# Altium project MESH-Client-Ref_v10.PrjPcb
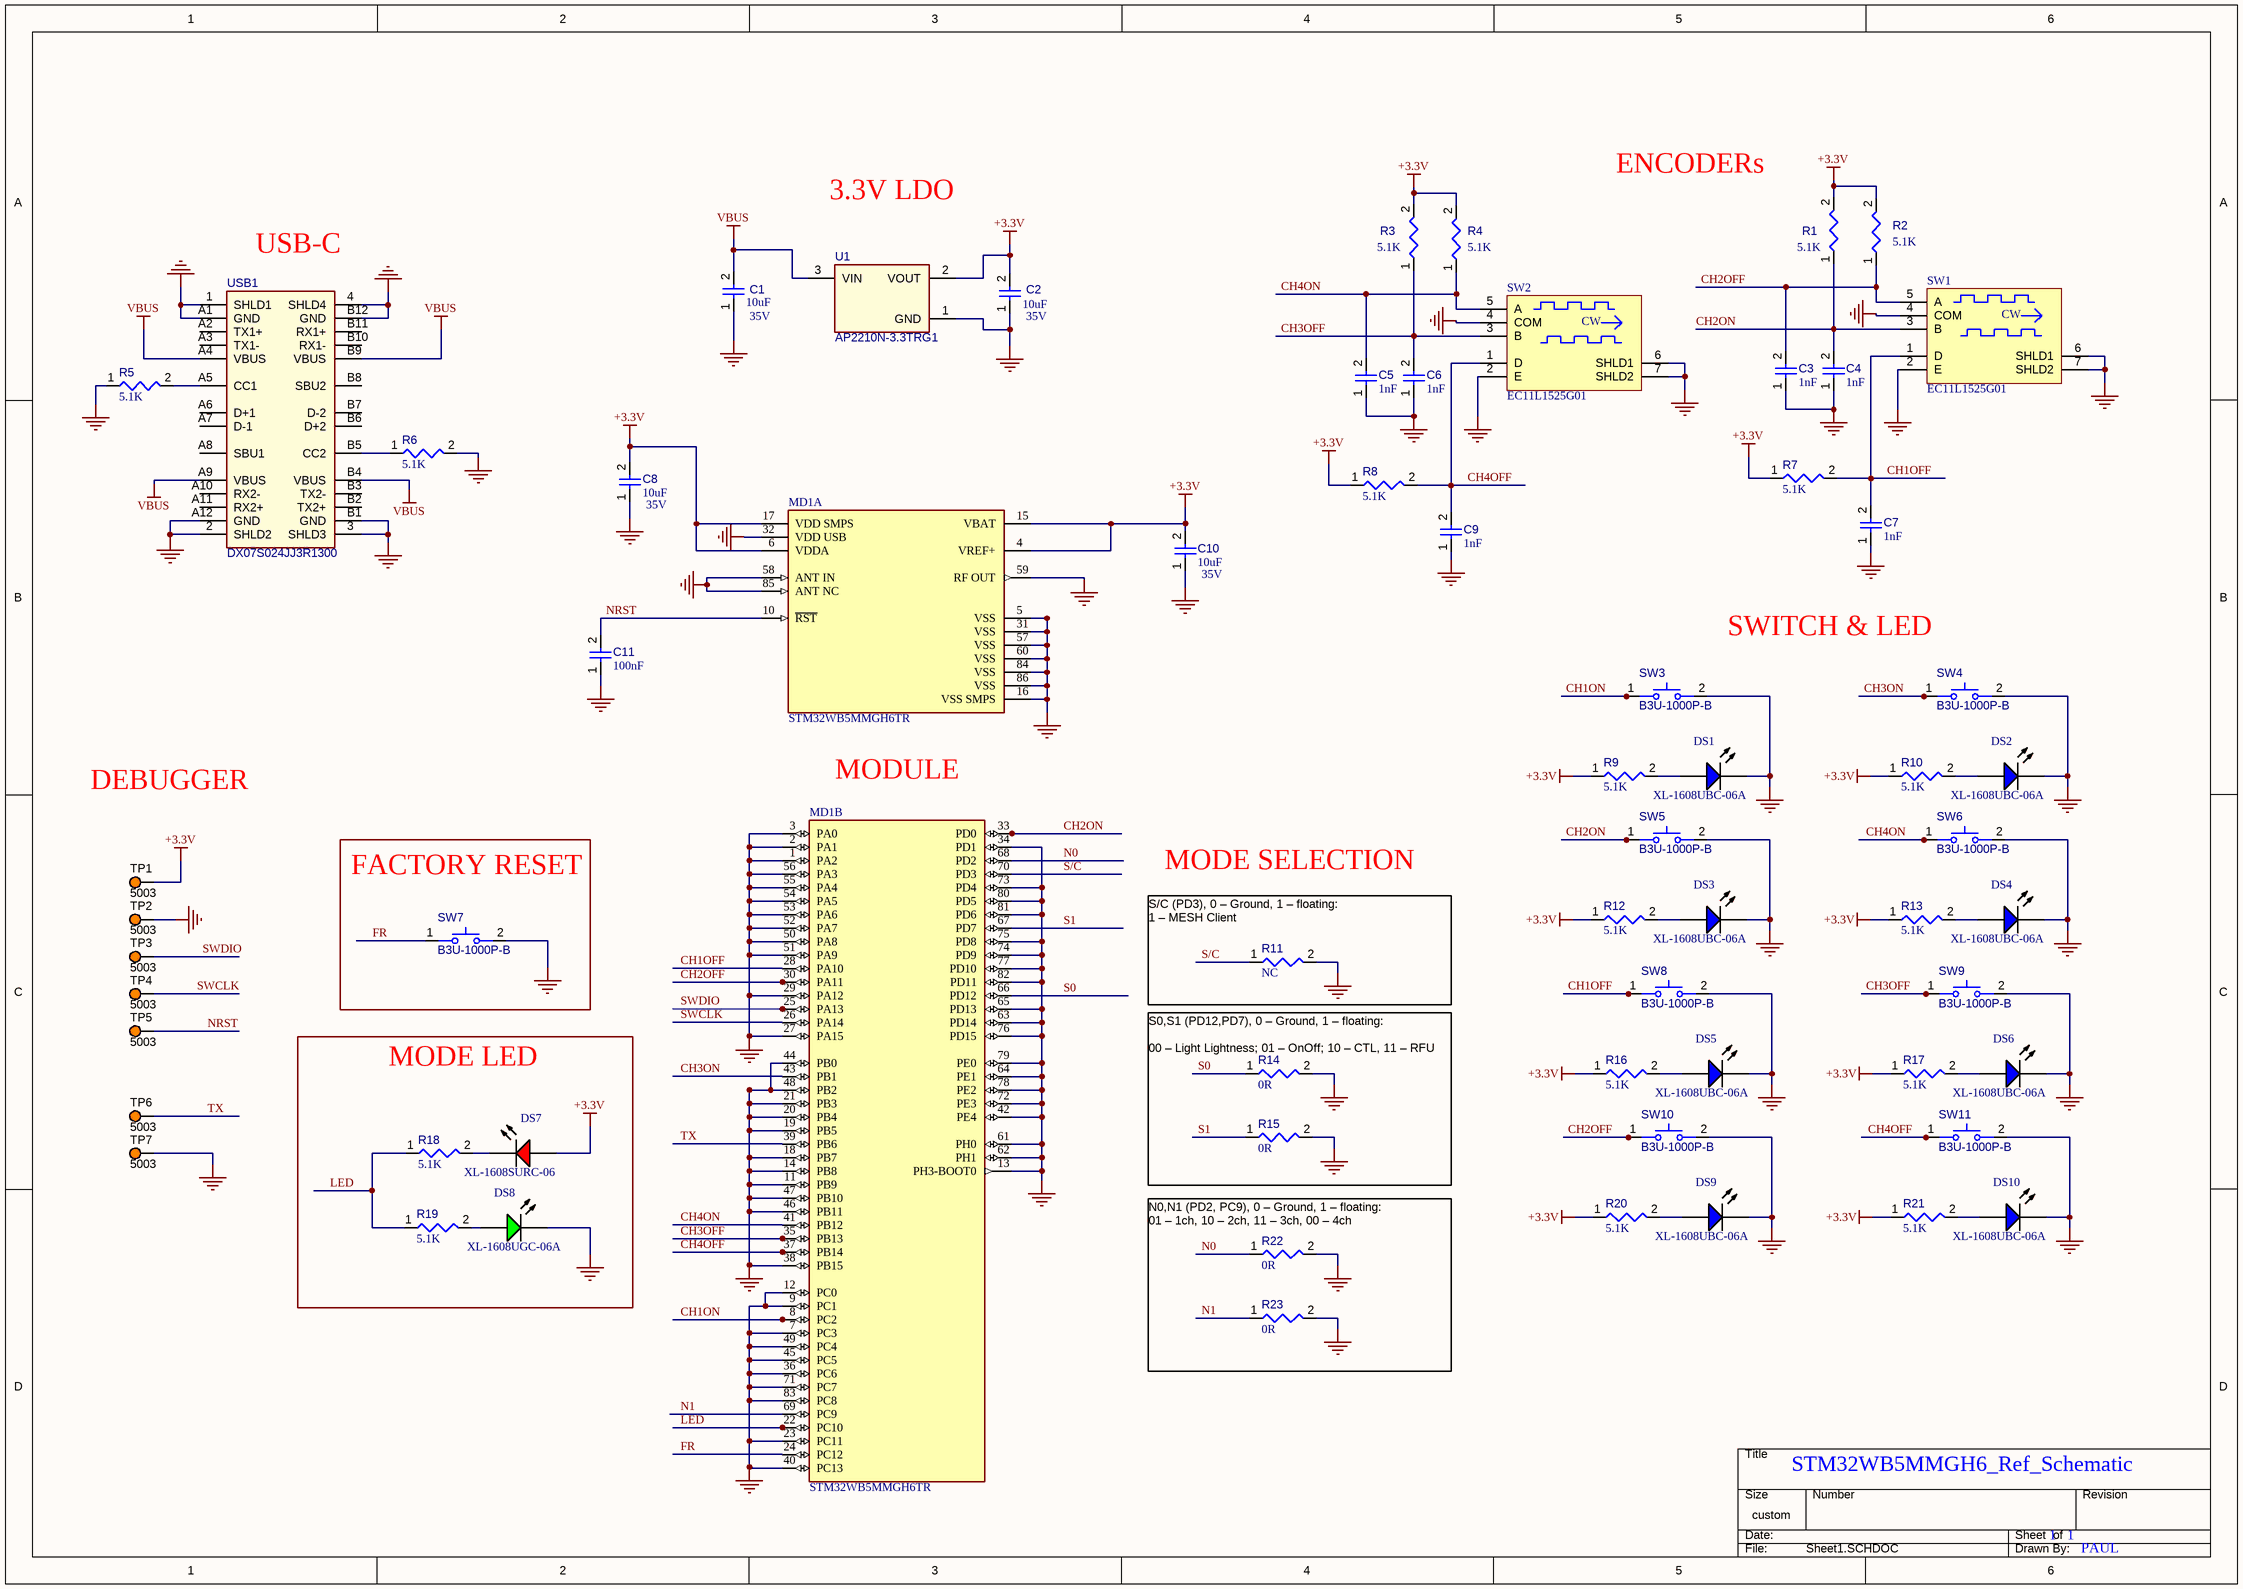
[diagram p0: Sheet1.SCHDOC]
1 sheet, 65 parts. Net scope: global (net labels, ports and power ports of the same name join across sheets).
Board file: PCB1.PcbDoc

## Sheet Sheet1.SCHDOC
size 420 x 297 mm; SheetNumber: 1; SheetTotal: 1

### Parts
C1  Voltage Rating: 35V  [C0603]  (hidden comment: 10uF)
C2  Voltage Rating: 35V  [C0603]  (hidden comment: 10uF)
C3  1nF  [C0603]
C4  1nF  [C0603]
C5  1nF  [C0603]
C6  1nF  [C0603]
C7  1nF  [C0603]
C8  Voltage Rating: 35V  [C0603]  (hidden comment: 10uF)
C9  1nF  [C0603]
C10  Voltage Rating: 35V  [C0603]  (hidden comment: 10uF)
C11  value 100nF  [C0603]  (hidden comment: 0.1uF)
DS1  XL-1608UBC-06A  [LED0603]
DS2  XL-1608UBC-06A  [LED0603]
DS3  XL-1608UBC-06A  [LED0603]
DS4  XL-1608UBC-06A  [LED0603]
DS5  XL-1608UBC-06A  [LED0603]
DS6  XL-1608UBC-06A  [LED0603]
DS7  XL-1608SURC-06  [LED0603]
DS8  XL-1608UGC-06A  [LED0603]
DS9  XL-1608UBC-06A  [LED0603]
DS10  XL-1608UBC-06A  [LED0603]
MD1  STM32WB5MMGH6TR  [FP-STM32WB5MMGH6TR-MFG]  (parts A,B of 2)
R1  5.1K  [R0603]
R2  5.1K  [R0603]
R3  5.1K  [R0603]
R4  5.1K  [R0603]
R5  5.1K  [R0603]
R6  5.1K  [R0603]
R7  5.1K  [R0603]
R8  5.1K  [R0603]
R9  5.1K  [R0603]
R10  5.1K  [R0603]
R11  NC  [R0402]  (no BOM)
R12  5.1K  [R0603]
R13  5.1K  [R0603]
R14  0R  [R0402]
R15  0R  [R0402]
R16  5.1K  [R0603]
R17  5.1K  [R0603]
R18  5.1K  [R0603]
R19  5.1K  [R0603]
R20  5.1K  [R0603]
R21  5.1K  [R0603]
R22  0R  [R0402]
R23  0R  [R0402]
SW1  EC11L1525G01  [EC11L1525G01]
SW2  EC11L1525G01  [EC11L1525G01]
SW3  B3U-1000P-B  [OMRON-B3U-1000P-2-B_V]
SW4  B3U-1000P-B  [OMRON-B3U-1000P-2-B_V]
SW5  B3U-1000P-B  [OMRON-B3U-1000P-2-B_V]
SW6  B3U-1000P-B  [OMRON-B3U-1000P-2-B_V]
SW7  B3U-1000P-B  [OMRON-B3U-1000P-2-B_V]
SW8  B3U-1000P-B  [OMRON-B3U-1000P-2-B_V]
SW9  B3U-1000P-B  [OMRON-B3U-1000P-2-B_V]
SW10  B3U-1000P-B  [OMRON-B3U-1000P-2-B_V]
SW11  B3U-1000P-B  [OMRON-B3U-1000P-2-B_V]
TP1  5003  [KSTN-5003]  (no BOM)
TP2  5003  [KSTN-5003]  (no BOM)
TP3  5003  [KSTN-5003]  (no BOM)
TP4  5003  [KSTN-5003]  (no BOM)
TP5  5003  [KSTN-5003]  (no BOM)
TP6  5003  [KSTN-5003]  (no BOM)
TP7  5003  [KSTN-5003]  (no BOM)
U1  AP2210N-3.3TRG1  [SOT23-3]
USB1  DX07S024JJ3R1300  [JAE-DX07S024JJ3_V]

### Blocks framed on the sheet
FACTORY RESET: SW7
MODE LED: DS7 DS8 R18 R19

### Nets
+3.3V: C2.2 C8.2 C10.2 DS7.1(A) MD1.4(VREF+) MD1.6(VDDA) MD1.15(VBAT) MD1.17(VDD_SMPS) R1.2 R2.2 R3.2 R4.2 R7.1 R8.1 R9.1 R10.1 R12.1 R13.1 R16.1 R17.1 R20.1 R21.1 TP1.1 U1.2(VOUT)
GND: C1.1 C2.1 C3.1 C4.1 C5.1 C6.1 C7.1 C8.1 C9.1 C10.1 C11.1 DS1.2(K) DS2.2(K) DS3.2(K) DS4.2(K) DS5.2(K) DS6.2(K) DS8.2(K) DS9.2(K) DS10.2(K) MD1.1(PA2) MD1.2(PA1) MD1.3(PA0) MD1.5(VSS) MD1.7(PC3) MD1.9(PC1) MD1.11(PB9) MD1.12(PC0) MD1.13(PH3-BOOT0) MD1.14(PB8) MD1.16(VSS_SMPS) MD1.18(PB7) MD1.19(PB5) MD1.20(PB4) MD1.21(PB3) MD1.23(PC11) MD1.27(PA15) MD1.29(PA12) MD1.31(VSS) MD1.32(VDD_USB) MD1.34(PD1) MD1.36(PC6) MD1.38(PB15) MD1.40(PC13) MD1.42(PE4) MD1.44(PB0) MD1.45(PC5) MD1.46(PB11) MD1.47(PB10) MD1.48(PB2) MD1.49(PC4) MD1.50(PA8) MD1.51(PA9) MD1.52(PA7) MD1.53(PA6) MD1.54(PA5) MD1.55(PA4) MD1.56(PA3) MD1.57(VSS) MD1.58(ANT_IN) MD1.59(RF_OUT) MD1.60(VSS) MD1.61(PH0) MD1.62(PH1) MD1.63(PD14) MD1.64(PE1) MD1.65(PD13) MD1.71(PC7) MD1.72(PE3) MD1.73(PD4) MD1.74(PD9) MD1.75(PD8) MD1.76(PD15) MD1.77(PD10) MD1.78(PE2) MD1.79(PE0) MD1.80(PD5) MD1.81(PD6) MD1.82(PD11) MD1.83(PC8) MD1.84(VSS) MD1.85(ANT_NC) MD1.86(VSS) R5.1 R6.2 R11.2 R14.2 R15.2 R22.2 R23.2 SW1.2(E) SW1.4(COM) SW1.6(SHLD1) SW1.7(SHLD2) SW2.2(E) SW2.4(COM) SW2.6(SHLD1) SW2.7(SHLD2) SW3.2 SW4.2 SW5.2 SW6.2 SW7.2 SW8.2 SW9.2 SW10.2 SW11.2 TP2.1 TP7.1 U1.1(GND) USB1.1(SHLD1) USB1.2(SHLD2) USB1.3(SHLD3) USB1.4(SHLD4) USB1.A1(GND) USB1.A12(GND) USB1.B1(GND) USB1.B12(GND)
VBUS: C1.2 U1.3(VIN) USB1.A4(VBUS) USB1.A9(VBUS) USB1.B4(VBUS) USB1.B9(VBUS)
CH1OFF: C7.2 MD1.28(PA10) R7.2 SW1.1(D) SW8.1
CH1ON: MD1.8(PC2) SW3.1
CH2OFF: C3.2 MD1.30(PA11) R2.1 SW1.5(A) SW10.1
CH2ON: C4.2 MD1.33(PD0) R1.1 SW1.3(B) SW5.1
CH3OFF: C6.2 MD1.35(PB13) R3.1 SW2.3(B) SW9.1
CH3ON: MD1.43(PB1) SW4.1
CH4OFF: C9.2 MD1.37(PB14) R8.2 SW2.1(D) SW11.1
CH4ON: C5.2 MD1.41(PB12) R4.1 SW2.5(A) SW6.1
FR: MD1.24(PC12) SW7.1
LED: MD1.22(PC10) R18.1 R19.1
N0: MD1.68(PD2) R22.1
N1: MD1.69(PC9) R23.1
NRST: C11.2 MD1.10(~{RST}) TP5.1
S0: MD1.66(PD12) R14.1
S1: MD1.67(PD7) R15.1
S/C: MD1.70(PD3) R11.1
SWCLK: MD1.26(PA14) TP4.1
SWDIO: MD1.25(PA13) TP3.1
TX: MD1.39(PB6) TP6.1
NetDS1_1: DS1.1(A) R9.2
NetDS2_1: DS2.1(A) R10.2
NetDS3_1: DS3.1(A) R12.2
NetDS4_1: DS4.1(A) R13.2
NetDS5_1: DS5.1(A) R16.2
NetDS6_1: DS6.1(A) R17.2
NetDS7_2: DS7.2(K) R18.2
NetDS8_1: DS8.1(A) R19.2
NetDS9_1: DS9.1(A) R20.2
NetDS10_1: DS10.1(A) R21.2
NetR5_2: R5.2 USB1.A5(CC1)
NetR6_1: R6.1 USB1.B5(CC2)

Not connected (* = marked no-connect by the designer): USB1 A2(TX1+) A3(TX1-) A6(D+1) A7(D-1) A8(SBU1) A10(RX2-) A11(RX2+) B2(TX2+) B3(TX2-) B6(D+2) B7(D-2) B8(SBU2) B10(RX1-) B11(RX1+)

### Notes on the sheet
- ENCODERs
- (near USB1) USB-C
- 3.3V LDO
- SWITCH & LED
- DEBUGGER
- (near MD1) MODULE
- MODE SELECTION
- (near R11) S/C (PD3), 0 – Ground, 1 – floating:
  1 – MESH Client
- S0,S1 (PD12,PD7), 0 – Ground, 1 – floating:
  00 – Light Lightness; 01 – OnOff; 10 – CTL, 11 – RFU
- N0,N1 (PD2, PC9), 0 – Ground, 1 – floating:
  01 – 1ch, 10 – 2ch, 11 – 3ch, 00 – 4ch
- STM32WB5MMGH6_Ref_Schematic
- 1   1
- PAUL

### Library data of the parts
C1 C2 C8 C10 = C0603_10U: CAP CER 10UF 35V X5R 0603; Part Number: GRM188R6YA106MA73D; Manufacturer: Murata
C3-C7 C9 = C0603-1N: CAP CER 1000PF 50V C0G/NP0 0603; Manufacturer: Murata Electronics; Part Number: GRM1885C1H102JA01D
C11 = C0603-0.1U: CAP CER 0.1UF 16V X7R 0603; Manufacturer: Murata Electronics; Part Number: GCJ188R71C104KA01D
DS1-DS6 DS9 DS10 = XL-1608UBC-06A: CHIP LED 0603 BLUE SMD; Manufacturer: XINGLIGHT
DS7 = XL-1608SURC-06: CHIP LED 0603 RED SMD; Manufacturer: XINGLIGHT
DS8 = XL-1608UGC-06A: CHIP LED 0603 GREEN SMD; Manufacturer: XINGLIGHT
MD1 = STM32WB5MMGH6TR: ULTRA-LOW-POWER DUAL CORE ARM CO; Manufacturer: STMicroelectronics; Part Number: PX32WB5MMGH6TR
R1-R10 R12 R13 R16-R21 = R0603-5.1K: RES 5.1K OHM 1% 1/10W 0603; Manufacturer: Yageo; Part Number: RC0603FR-075K1L
R11 = R0402-NC: RES NC 0402
R14 R15 R22 R23 = R0402-0R: RES 0 OHM JUMPER 1/16W 0402; Manufacturer: Yageo; Part Number: RC0402FR-070RL
SW1 SW2 = EC11L1525G01: Plugin Rotary Encoders ROHS; Manufacturer: ALPSALPINE
SW3-SW11 = B3U-1000P-B: Ultra-small Surface-mounting Tactile Switches with High Contact Reliability, SPST-NO, -25 to 70 degC, 2-Pin SMD, RoHS, Tape and Reel; Manufacturer: Omron; Voltage Rating: 12V
TP1-TP7 = CMP-002-00037-2: Test Point, Orange, Height 4.6 mm, Tail Length 3 mm, 1-Pin THD, RoHS; Manufacturer: Keystone
U1 = AP2210N-3.3TRG1: IC REG LINEAR 3.3V 300MA SOT23-3; Manufacturer: Diodes Incorporated
USB1 = DX07S024JJ3R1300: USB-C Connector, 20 V, 1.25 A, -30 to 80 degC, RoHS, Tape and Reel; Manufacturer: JAE Electronics; Gender: Receptacle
